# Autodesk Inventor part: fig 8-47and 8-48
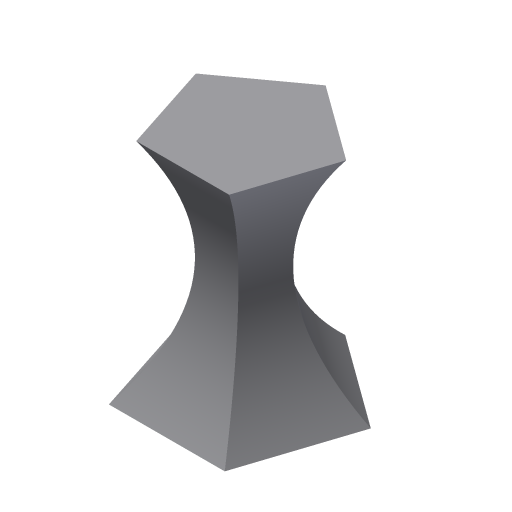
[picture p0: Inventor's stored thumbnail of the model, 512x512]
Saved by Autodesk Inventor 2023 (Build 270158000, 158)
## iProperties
Part Number: fig 8-47and 8-48
Document SubType Name: Modeling
Created: 2002-12
Designer: deepak
Density: 1 g/cm^3
Material: Generic
Appearance: Default
Control State: 0
Master: False
Checked Out: False
Shininess: 64.0
Length Units: 11269
Angle Units: 11279
Time Units: 11290
Mass Units: 11283
Length Display Precision: 3
Angle Display Precision: 2
Compacted: True
Density: 0.0
Volumn: 0.0
Area: 0.0
PropertySet Name: Model Information
Author: deepak
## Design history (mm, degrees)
sketch "Sketch1"
  geometry: L1 (0, 21.819)-(20.751, 6.743); L2 (20.751, 6.743)-(12.825, -17.652); L3 (12.825, -17.652)-(-12.825, -17.652); L4 (-12.825, -17.652)-(-20.751, 6.743); L5 (-20.751, 6.743)-(0, 21.819); 1 further point
  constraints: 10 end point, 9 other
workplane "Work Plane1"
sketch "Sketch2"
  geometry: L1 (0, 8.24)-(7.836, 2.546); L2 (7.836, 2.546)-(4.843, -6.666); L3 (4.843, -6.666)-(-4.843, -6.666); L4 (-4.843, -6.666)-(-7.836, 2.546); L5 (-7.836, 2.546)-(0, 8.24); 1 further point
  constraints: 10 end point, 9 other
workplane "Work Plane2"
sketch "Sketch3"
  geometry: L1 (0, 17.494)-(16.637, 5.406); L2 (16.637, 5.406)-(10.283, -14.153); L3 (10.283, -14.153)-(-10.283, -14.153); L4 (-10.283, -14.153)-(-16.637, 5.406); L5 (-16.637, 5.406)-(0, 17.494); 1 further point
  constraints: 10 end point, 9 other
loft "Loft4" sketch "Sketch3" dims "d20" = 0, "d21" = 90 deg, "d22" = 0, "d23" = 90 deg, "d24" = 0, "d25" = 90 deg
body "Solid1"
other parameters: "d0" = 25, "d1" = 25
